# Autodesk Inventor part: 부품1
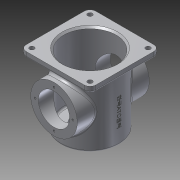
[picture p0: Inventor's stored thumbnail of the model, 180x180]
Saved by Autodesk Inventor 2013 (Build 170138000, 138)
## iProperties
Created: 2015-10
Part Number: 부품1
Material: 알루미늄 6061
Document SubType Name: Modeling
Designer: Administrator
Density: 2.71 g/cm^3
Mass: 990.636 g
Surface Area: 1049.62 cm^2
Volume: 365.548 cm^3
Author: Administrator
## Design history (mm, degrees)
sketch "스케치1"
  geometry: L1 (0, 0)-(50, 0); L2 (78.014, 0)-(78.014, -40); L3 (50, -40)-(50, -120); L4 (0, -125)-(0, 0); L5 (40, -120)-(40, -125); L6 (40, -125)-(0, -125); L7 (40, -125)-(40, -120); L8 (40, -120)-(50, -120); L9 (50, -40)-(50, 0); L10 (27, -125)-(27, -112); L11 (27, -112)-(45, -112); L12 (45, -112)-(45, 0)
  constraints: 24 end point, 7 perpendicular, 4 parallel, 2 point on line, 1 horizontal
  dimensions: "d0" = 50 distance between parallel lines of L4 L3; "d2" = 40 distance between parallel lines of L4 L7; "d4" = 125 distance between parallel lines of L1 L6; "d5" = 120 distance between parallel lines of L1 L8; "d6" = 27 distance between parallel lines of L4 L10; "d7" = 13 distance between parallel lines of L10 L5 (derived); "d8" = 13 distance between parallel lines of L11 L6; "d9" = 5 distance between parallel lines of L12 L3
revolve "회전1" stored, may be unused: angle "d10" = 90 deg
sketch "스케치3"
  geometry: L1 (-60, 60)-(60, 60); L2 (60, 60)-(60, -60); L3 (60, -60)-(-60, -60); L4 (-60, -60)-(-60, 60); C1 r 50 at (0, 0) reference; 2 further points
  constraints: 8 end point, 2 midpoint, 2 parallel, 1 horizontal, 1 horizontal alignment, 1 perpendicular, 1 vertical alignment
  dimensions: "d15" = 120 distance of L1.end L2.end; "d17" = 120 distance of L1.start L1.end
extrude "돌출1" join sketch "스케치3" distance "d18" = 10; taper "d19" = 0 deg
node "작업 평면1"
sketch "스케치4"
  geometry: C1 r 40 at (0, -60); 1 further point
  constraints: 1 centre point, 1 vertical alignment
  dimensions: "d21" = 80 diameter of C1; "d23" = 60 distance of point (0, 0) C1.centre
extrude "돌출2" join sketch "스케치4" distance "d24" = 124; taper "d25" = 0 deg
hole "구멍1" diameter "d28" = 54; stored, may be unused: countersink angle "d32" = 90 deg, drill point angle "d34" = 118 deg; dims "d26" = 10, "d27" = 10, "d29" = 6, "d30" = 4, "d31" = 2, "d33" = 8
fillet "모깎기1" dims "d35" = 10
fillet "모깎기2" dims "d36" = 3
sketch "스케치5"
  geometry: C1 r 40 at (0, 0) reference; A1 r 32.5 centre (0, 0) between (0, 32.5) and (-32.5, 0); 3 further points
  constraints: 4 point on circle, 1 centre point, 1 coincident
  dimensions: "d37" = 65 diameter of A1
sketch "스케치6"
  geometry: C1 r 40 at (0, 0) reference; A1 r 32.5 centre (0, 0) between (0, 32.5) and (0, -32.5); 3 further points
  constraints: 4 point on circle, 1 centre point, 1 coincident
  dimensions: "d39" = 65 diameter of A1
hole "구멍2" sketch "스케치5" diameter "d41" = 3.459; stored, may be unused: countersink angle "d45" = 90 deg, drill point angle "d47" = 118 deg; dims "d42" = 8, "d43" = 4, "d44" = 2, "d46" = 10
hole "구멍3" sketch "스케치6" diameter "d48" = 3.459; stored, may be unused: countersink angle "d52" = 90 deg, drill point angle "d54" = 118 deg; dims "d49" = 8, "d50" = 4, "d51" = 2, "d53" = 10
sketch "스케치7"
  geometry: C1 r 4 at (0, 110); C2 r 4 at (100, 110); C3 r 4 at (100, 10); C4 r 4 at (0, 10); A1 r 10 centre (0, 10) between (-10, 10) and (0, 0) reference; A2 r 10 centre (100, 10) between (100, 0) and (110, 10) reference; A3 r 10 centre (100, 110) between (110, 110) and (100, 120) reference; A4 r 10 centre (0, 110) between (0, 120) and (-10, 110) reference
  constraints: 4 centre point, 4 coincident
  dimensions: "d55" = 8 diameter of C1; "d57" = 8 diameter of C2; "d58" = 8 diameter of C3; "d59" = 8 diameter of C4
extrude "돌출3" cut sketch "스케치7" distance "d60" = 124; taper "d61" = 0 deg
sketch "스케치8"
  geometry: L1 (-92.542, 0)-(92.542, 0); L2 (-56.585, -56.585)-(56.585, 56.585); L3 (98.99, -98.99)-(-98.99, 98.99); C1 r 27 at (0, 0) reference; C2 r 40 at (0, 0) reference; A1 r 32.5 centre (0, 0) between (-22.981, 22.981) and (-22.981, -22.981); 3 further points
  constraints: 6 end point, 4 point on circle, 4 point on line, 3 midpoint, 2 coincident, 1 centre point, 1 horizontal
  dimensions: "d62" = 65 diameter of A1; "d64" = 45 deg angle of L1 L2; "d66" = 45 deg angle of L3 L1
hole "구멍4" sketch "스케치8" at (-22.981, 22.981), (-22.981, -22.981), (22.981, -22.981), (22.981, 22.981) diameter "d68" = 3.459; stored, may be unused: countersink angle "d72" = 90 deg, drill point angle "d74" = 118 deg; dims "d69" = 8, "d70" = 4, "d71" = 2, "d73" = 10
fillet "모깎기3" dims "d75" = 5
fillet "모깎기4" dims "d76" = 5
fillet "모깎기5" dims "d77" = 5
revolve "회전2" stored, may be unused: angle "d78" = 90 deg
chamfer "모따기1" distance "d79" = 1; stored, may be unused: second distance "d80" = 2, angle "d81" = 45 deg
node "작업 평면2"
node "작업 평면4"
sketch "스케치11"
  geometry: L1 (50, 0)-(-50, 0) reference; 3 further points
  constraints: 1 midpoint, 1 vertical alignment, 1 other
  dimensions: "d90" = 70 distance from line of point (0, -70) L1
feature "엠보싱1" sketch "스케치11" dims "d0" = 50, "d2" = 40, "d4" = 125, "d5" = 120, "d6" = 27, "d7" = 13 (derived), "d8" = 13, "d9" = 5, "d15" = 120, "d17" = 120, "d88" = 0.5, "d89" = 0
fillet "모깎기7" dims "d91" = 3
fillet "모깎기8" dims "d92" = 3
chamfer "모따기2" distance "d93" = 3; stored, may be unused: second distance "d94" = 2, angle "d95" = 45 deg
node "솔리드1"
other parameters: "d20" = 62
